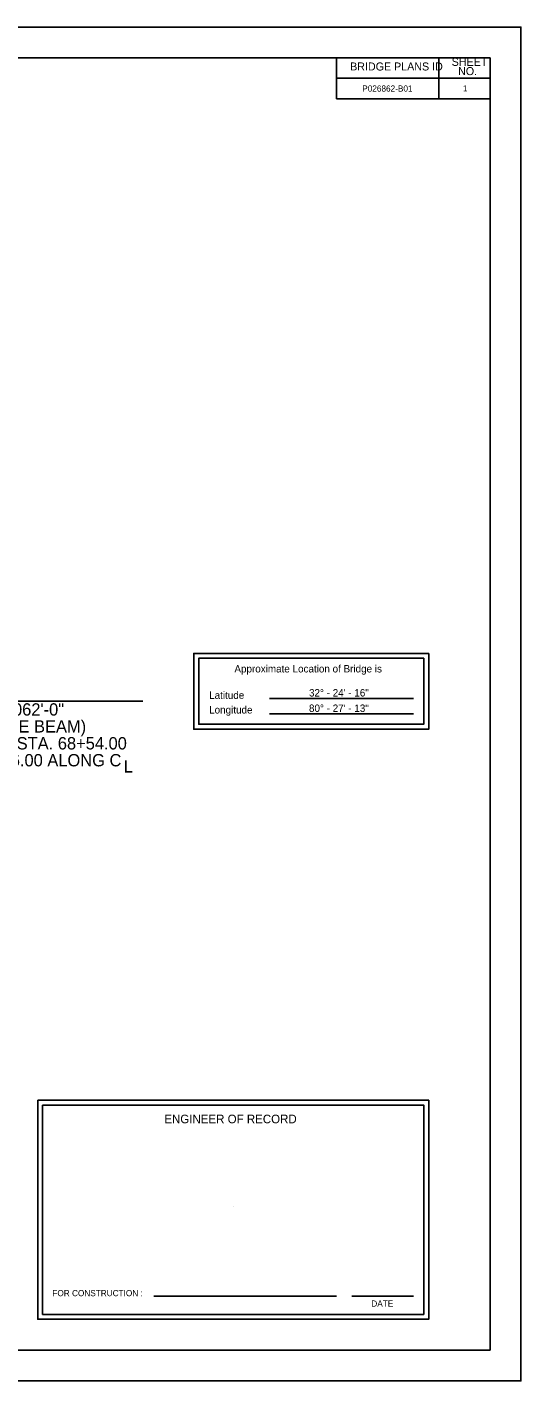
# Model space of a CAD drawing. Extents: x 1034.1 to 1070.1, y 1567.5 to 1589.5.
# Drawn here: x 1062.08 to 1070.11, y 1567.5 to 1589.5 of the extents above; entities that cross this region are included whole.
import ezdxf

# ---------------------------------------------------------------- set-up
doc = ezdxf.new("R2010")
doc.units = 0
for name, color, linetype in [('BR_BORDER LINES', 7, 'Continuous'), ('Level 3', 7, 'Continuous'), ('Plan Sheet CELL', 7, 'Continuous'), ('Sheet Plot Border Outside CELL', 7, 'Continuous')]:
    doc.layers.add(name, color=color, linetype=linetype)

msp = doc.modelspace()

# ---------------------------------------------------------------- linework, layer by layer
at = {"layer": 'BR_BORDER LINES'}
for p, q in [((1036.11, 1588.996), (1069.61, 1588.996)), ((1067.11, 1588.33), (1067.11, 1588.996)), ((1068.777, 1588.33), (1068.777, 1588.996)), ((1069.61, 1567.998), (1069.61, 1588.996)), ((1067.11, 1588.667), (1069.61, 1588.667)), ((1069.61, 1588.33), (1067.11, 1588.33)), ((1069.61, 1580.783), (1069.61, 1587.832)), ((1036.11, 1567.998), (1069.61, 1567.998))]:
    msp.add_line(p, q, dxfattribs=at)
at = {"layer": 'Level 3'}
for p, q in [((1063.958, 1578.545), (1059.873, 1578.545)), ((1065.43, 1570.328), (1065.43, 1570.328))]:
    msp.add_line(p, q, dxfattribs=at)
at = {"layer": 'Plan Sheet CELL'}
for p, q in [((1066.018, 1578.587), (1068.36, 1578.587)), ((1066.018, 1578.337), (1068.36, 1578.337)), ((1064.139, 1568.873), (1067.11, 1568.873)), ((1067.36, 1568.873), (1068.36, 1568.873))]:
    msp.add_line(p, q, dxfattribs=at)
for points in [[(1068.61, 1579.319), (1064.789, 1579.319), (1064.789, 1578.087), (1068.61, 1578.087)], [(1068.53, 1579.239), (1064.869, 1579.239), (1064.869, 1578.167), (1068.53, 1578.167)], [(1062.25, 1572.058), (1068.61, 1572.058), (1068.61, 1568.498), (1062.25, 1568.498)], [(1062.33, 1571.978), (1068.53, 1571.978), (1068.53, 1568.578), (1062.33, 1568.578)]]:
    msp.add_lwpolyline(points, close=True, dxfattribs=at)
at = {"layer": 'Sheet Plot Border Outside CELL'}
msp.add_lwpolyline([(1034.11, 1589.496), (1070.11, 1589.496), (1070.11, 1567.496), (1034.11, 1567.496)], close=True, dxfattribs=at)

# ---------------------------------------------------------------- texts
at = {"layer": 'Level 3'}
for s, height, p in [('BRIDGE PLANS ID', 0.13, (1067.332, 1588.791)), ('SHEET', 0.13, (1068.983, 1588.866)), ('NO.', 0.13, (1069.088, 1588.716)), ('P026862-B01', 0.1, (1067.529, 1588.448)), ('1', 0.1, (1069.167, 1588.45)), (' CONSTRUCT 3062\'-0"', 0.2, (1059.873, 1578.308)), (' (P.S. CONCRETE BEAM)', 0.2, (1059.873, 1578.033)), (' BRIDGE FROM STA. 68+54.00', 0.2, (1059.873, 1577.758)), (' TO STA. 104+56.00 ALONG C', 0.2, (1059.873, 1577.483)), ('L', 0.2, (1063.649, 1577.383))]:
    msp.add_text(s, height=height, dxfattribs=at).set_placement(p)
at = {"layer": 'Plan Sheet CELL'}
for s, height, p in [('Approximate Location of Bridge is', 0.12, (1065.45, 1579.009)), ('32° - 24\' - 16"', 0.12, (1066.663, 1578.618)), ('Latitude', 0.12, (1065.039, 1578.58)), ('Longitude', 0.12, (1065.039, 1578.342)), ('80° - 27\' - 13"', 0.12, (1066.663, 1578.368)), ('ENGINEER OF RECORD', 0.14, (1064.31, 1571.683)), ('FOR CONSTRUCTION :', 0.1, (1062.489, 1568.873)), ('DATE', 0.1, (1067.677, 1568.704))]:
    msp.add_text(s, height=height, dxfattribs=at).set_placement(p)

doc.saveas('drawing.dxf')
